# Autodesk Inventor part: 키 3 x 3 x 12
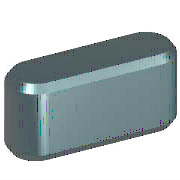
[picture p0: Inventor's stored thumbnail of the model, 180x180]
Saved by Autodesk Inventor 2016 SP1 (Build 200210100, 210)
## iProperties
Created: 2012-02
Part Number: 키 3 x 3 x 12
Material: 강철, 연강
Description: 키 및 해당 키홈
Document SubType Name: Modeling
Standard: KS B 1311
Designer: mduedu
Standards Organization: KS
Language: ko-KR
Size Designation: 3 x 3 x 12
Categories: <MemberInstance><Categories><Category DisplayName="샤프트 부품" InternalName="7f7aeb1f-a693-4053-b835-cee3144e0d98" Mnemonic="SHFT"><Category DisplayName="키" Interna
Density: 1 g/cm^3
Appearance: 노란색
IsCustomPart: 1
Author: mduedu
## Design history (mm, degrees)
workplane "Work Plane1"
workplane "Work Plane2"
sketch "스케치1"
  geometry: L1 (1.5, 1.5)-(10.5, 1.5); L2 (10.5, -1.5)-(1.5, -1.5); L3 (0, 9.4)-(0, -7.4) reference; L4 (-5, 0)-(30, 0) reference; L5 (12, 0)-(12, 7); A1 r 1.5 centre (1.5, 0) between (1.5, 1.5) and (1.5, -1.5); A2 r 1.5 centre (10.5, 0) between (10.5, -1.5) and (10.5, 1.5)
  constraints: 6 end point, 5 point on circle, 4 tangent, 3 point on line, 2 centre point, 1 horizontal, 1 parallel, 1 perpendicular
  dimensions: "d0" = 1.5 radius of A1 (= 0.5 x PB); "d13" = 1.5 radius of A2 (= 0.5 x PB); "d14" = 12 distance between parallel lines of L5 L3 (= NLG)
extrude "본체1" new body sketch "스케치1" taper "d3" = 0 deg; stored distance "d4" = 10
workplane "Work Plane3"
body "Solid1"
chamfer "모따기1" distance "d8" = 0.25 (= PHH); stored, may be unused: second distance "d9" = 0.25 (= PHH), angle "d15" = 45 deg
other parameters: "d1" = -1.8 (= -PNT), "d2" = 1.2 (= PH - PNT), "NLG" = 12 [user parameter; used in 3 equation terms], "PB" = 3 [user parameter; used in 2 equation terms], "PNT" = 1.8 [user parameter; used in 2 equation terms], "PH" = 3 [user parameter; used in 1 equation term], "PHH" = 0.25 [user parameter; used in 2 equation terms], "d10" = 0, "d16" = 0, "d17" = 0, "d18" = 0, "WDMIN" = 8 [user parameter], "PLB2" = 12 (= NLG) [user parameter], "PLB1" = 12 (= NLG) [user parameter], "RR" = 0.08 [user parameter], "PUEB" = 1.4 [user parameter]
